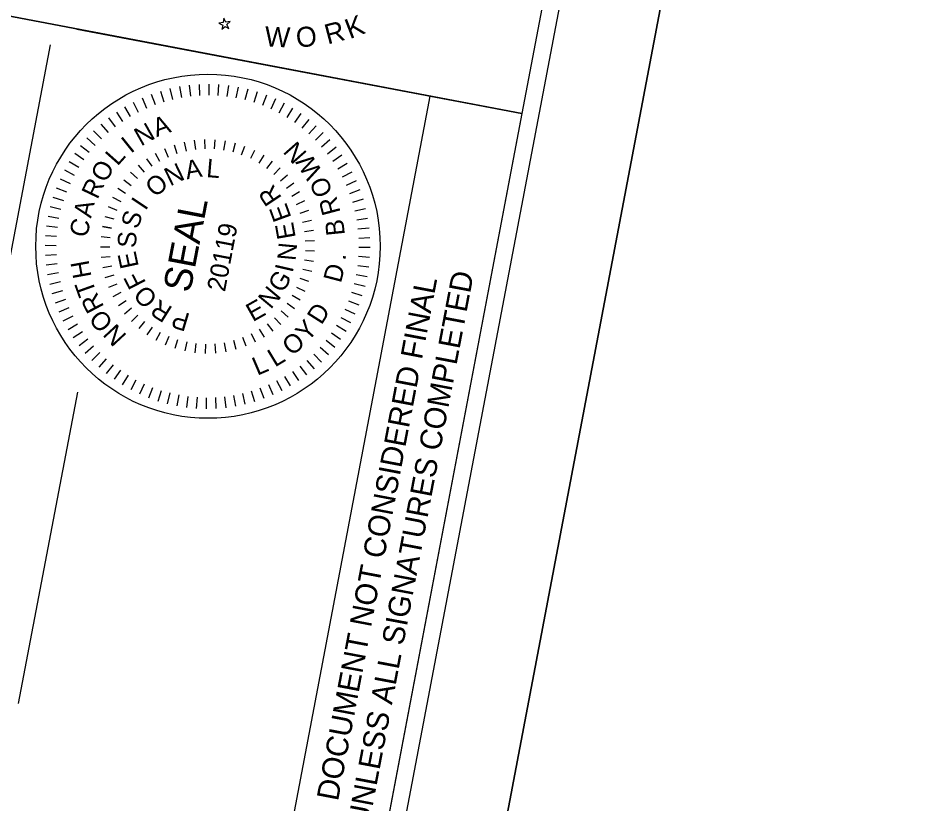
# Model space of a CAD drawing. Extents: x 1615642 to 1617075, y 899305 to 901510.
# Drawn here: x 1616848.8 to 1617075.3, y 900421.5 to 900619.3 of the extents above; entities that cross this region are included whole.
import ezdxf

# ---------------------------------------------------------------- set-up
doc = ezdxf.new("R2010")
doc.units = 0
for name, color, linetype in [('Default', 7, 'Continuous'), ('DEV BORDER CELL', 7, 'Continuous'), ('DEV DOT SWIRL SEAL CELL', 7, 'Continuous'), ('Sheet Plot Border Outside CELL', 7, 'Continuous'), ('Sheet Sticker Exception Certification CELL', 7, 'Continuous'), ('Text', 7, 'Continuous')]:
    doc.layers.add(name, color=color, linetype=linetype)

msp = doc.modelspace()

# ---------------------------------------------------------------- linework, layer by layer
at = {"layer": 'Default'}
for p, q in [((1616887.07, 900601.49), (1616887.72, 900598.78)), ((1616889.49, 900601.99), (1616889.97, 900599.25)), ((1616891.93, 900602.35), (1616892.24, 900599.58)), ((1616894.39, 900602.55), (1616894.54, 900599.77)), ((1616896.86, 900602.61), (1616896.84, 900599.82)), ((1616899.33, 900602.51), (1616899.14, 900599.74)), ((1616901.78, 900602.27), (1616901.43, 900599.51)), ((1616904.22, 900601.88), (1616903.7, 900599.15)), ((1616906.64, 900601.35), (1616905.95, 900598.65)), ((1616880.06, 900599.13), (1616881.18, 900596.58)), ((1616882.35, 900600.06), (1616883.32, 900597.45)), ((1616884.69, 900600.85), (1616885.5, 900598.18)), ((1616909.01, 900600.67), (1616908.16, 900598.01)), ((1616911.34, 900599.85), (1616910.33, 900597.25)), ((1616913.61, 900598.89), (1616912.45, 900596.35)), ((1616875.67, 900596.87), (1616877.1, 900594.47)), ((1616877.83, 900598.07), (1616879.11, 900595.59)), ((1616915.82, 900597.79), (1616914.51, 900595.33)), ((1616873.59, 900595.54), (1616875.15, 900593.24)), ((1616917.96, 900596.56), (1616916.5, 900594.18)), ((1616920.02, 900595.2), (1616918.43, 900592.92)), ((1616869.68, 900592.52), (1616871.51, 900590.43)), ((1616871.59, 900594.09), (1616873.29, 900591.89)), ((1616922.01, 900593.73), (1616920.27, 900591.54)), ((1616923.89, 900592.13), (1616922.03, 900590.06)), ((1616867.87, 900590.85), (1616869.82, 900588.86)), ((1616925.68, 900590.42), (1616923.69, 900588.47)), ((1616866.17, 900589.06), (1616868.24, 900587.2)), ((1616890.62, 900588.01), (1616891.14, 900585.75)), ((1616893.19, 900588.46), (1616893.48, 900586.16)), ((1616895.78, 900588.66), (1616895.85, 900586.34)), ((1616898.39, 900588.61), (1616898.23, 900586.3)), ((1616900.97, 900588.31), (1616900.59, 900586.02)), ((1616903.52, 900587.76), (1616902.92, 900585.52)), ((1616927.35, 900588.62), (1616925.26, 900586.78)), ((1616864.57, 900587.18), (1616866.75, 900585.44)), ((1616885.68, 900586.38), (1616886.63, 900584.26)), ((1616888.11, 900587.31), (1616888.85, 900585.11)), ((1616905.1, 900584.82), (1616905.91, 900587)), ((1616908.39, 900585.94), (1616907.37, 900583.86)), ((1616928.92, 900586.7), (1616926.72, 900585)), ((1616861.73, 900583.14), (1616864.11, 900581.67)), ((1616863.1, 900585.2), (1616865.37, 900583.6)), ((1616881.15, 900583.83), (1616882.48, 900581.92)), ((1616883.36, 900585.21), (1616884.49, 900583.19)), ((1616910.67, 900584.69), (1616909.45, 900582.71)), ((1616912.81, 900583.22), (1616911.41, 900581.37)), ((1616930.37, 900584.71), (1616928.07, 900583.14)), ((1616860.51, 900581), (1616862.97, 900579.68)), ((1616879.09, 900582.24), (1616880.6, 900580.47)), ((1616914.81, 900581.55), (1616913.24, 900579.84)), ((1616931.69, 900582.62), (1616929.3, 900581.2)), ((1616859.41, 900578.78), (1616861.94, 900577.62)), ((1616875.48, 900578.5), (1616877.29, 900577.06)), ((1616877.19, 900580.46), (1616878.87, 900578.85)), ((1616916.64, 900579.69), (1616914.91, 900578.14)), ((1616932.89, 900580.46), (1616930.42, 900579.19)), ((1616858.45, 900576.51), (1616861.05, 900575.5)), ((1616873.96, 900576.39), (1616875.91, 900575.13)), ((1616918.28, 900577.67), (1616916.41, 900576.3)), ((1616933.96, 900578.24), (1616931.41, 900577.11)), ((1616857.63, 900574.18), (1616860.28, 900573.33)), ((1616872.65, 900574.14), (1616874.71, 900573.07)), ((1616919.72, 900575.5), (1616917.72, 900574.31)), ((1616934.89, 900575.95), (1616932.27, 900574.98)), ((1616856.95, 900571.81), (1616859.65, 900571.12)), ((1616871.56, 900571.77), (1616873.72, 900570.91)), ((1616920.94, 900573.2), (1616918.84, 900572.21)), ((1616935.68, 900573.61), (1616933.01, 900572.8)), ((1616921.93, 900570.8), (1616919.74, 900570.01)), ((1616936.32, 900571.22), (1616933.61, 900570.58)), ((1616856.41, 900569.4), (1616859.15, 900568.87)), ((1616870.71, 900569.31), (1616872.94, 900568.66)), ((1616922.69, 900568.3), (1616920.43, 900567.74)), ((1616936.82, 900568.81), (1616934.08, 900568.32)), ((1616856.02, 900566.96), (1616858.78, 900566.6)), ((1616870.1, 900566.78), (1616872.38, 900566.35)), ((1616872.38, 900566.35), (1616870.1, 900566.78)), ((1616923.2, 900565.75), (1616920.9, 900565.4)), ((1616937.18, 900566.37), (1616934.4, 900566.05)), ((1616855.78, 900564.5), (1616858.56, 900564.31)), ((1616869.74, 900564.2), (1616872.05, 900563.99)), ((1616923.46, 900563.16), (1616921.14, 900563.04)), ((1616937.38, 900563.9), (1616934.6, 900563.76)), ((1616855.69, 900562.03), (1616858.47, 900562.01)), ((1616869.62, 900561.61), (1616871.94, 900561.61)), ((1616923.48, 900560.56), (1616921.16, 900560.66)), ((1616937.44, 900561.43), (1616934.65, 900561.46)), ((1616855.74, 900559.57), (1616858.52, 900559.71)), ((1616869.76, 900559.01), (1616872.07, 900559.24)), ((1616923.24, 900557.97), (1616920.94, 900558.29)), ((1616937.34, 900558.97), (1616934.57, 900559.16)), ((1616855.95, 900557.1), (1616858.72, 900557.42)), ((1616870.15, 900556.43), (1616872.43, 900556.89)), ((1616922.75, 900555.41), (1616920.49, 900555.95)), ((1616937.1, 900556.51), (1616934.34, 900556.87)), ((1616856.3, 900554.66), (1616859.05, 900555.14)), ((1616870.78, 900553.91), (1616873, 900554.58)), ((1616922.02, 900552.91), (1616919.82, 900553.67)), ((1616936.71, 900554.07), (1616933.98, 900554.59)), ((1616856.81, 900552.24), (1616859.51, 900552.89)), ((1616871.66, 900551.45), (1616873.81, 900552.34)), ((1616918.93, 900551.45), (1616921.04, 900550.48)), ((1616936.18, 900551.66), (1616933.48, 900552.35)), ((1616857.45, 900549.86), (1616860.12, 900550.67)), ((1616872.77, 900549.1), (1616874.82, 900550.19)), ((1616919.85, 900548.19), (1616917.84, 900549.36)), ((1616935.49, 900549.29), (1616932.84, 900550.13)), ((1616858.24, 900547.52), (1616860.85, 900548.49)), ((1616874.1, 900546.86), (1616876.04, 900548.15)), ((1616918.43, 900546), (1616916.54, 900547.36)), ((1616934.68, 900546.96), (1616932.08, 900547.96)), ((1616859.17, 900545.23), (1616861.71, 900546.36)), ((1616875.64, 900544.76), (1616877.44, 900546.23)), ((1616916.81, 900543.96), (1616915.06, 900545.5)), ((1616933.71, 900544.69), (1616931.18, 900545.84)), ((1616860.23, 900543.01), (1616862.71, 900544.28)), ((1616861.43, 900540.84), (1616863.82, 900542.27)), ((1616877.37, 900542.82), (1616879.03, 900544.45)), ((1616879.29, 900541.06), (1616880.78, 900542.84)), ((1616913.02, 900540.4), (1616911.6, 900542.24)), ((1616915, 900542.09), (1616913.41, 900543.79)), ((1616932.62, 900542.47), (1616930.15, 900543.78)), ((1616862.75, 900538.76), (1616865.06, 900540.33)), ((1616881.36, 900539.49), (1616882.67, 900541.41)), ((1616883.58, 900538.13), (1616884.7, 900540.16)), ((1616910.88, 900538.92), (1616909.65, 900540.88)), ((1616931.39, 900540.33), (1616929.01, 900541.79)), ((1616864.2, 900536.76), (1616866.41, 900538.46)), ((1616885.92, 900536.98), (1616886.84, 900539.12)), ((1616888.36, 900536.07), (1616889.06, 900538.28)), ((1616903.76, 900535.78), (1616903.14, 900538.01)), ((1616906.23, 900536.59), (1616905.4, 900538.76)), ((1616908.62, 900537.64), (1616907.58, 900539.72)), ((1616928.55, 900536.29), (1616926.37, 900538.02)), ((1616930.03, 900538.27), (1616927.75, 900539.87)), ((1616865.77, 900534.85), (1616867.87, 900536.68)), ((1616890.87, 900535.4), (1616891.37, 900537.67)), ((1616893.44, 900534.97), (1616893.71, 900537.28)), ((1616896.04, 900534.8), (1616896.08, 900537.12)), ((1616898.64, 900534.87), (1616898.46, 900537.19)), ((1616901.23, 900535.2), (1616900.82, 900537.49)), ((1616926.96, 900534.4), (1616924.89, 900536.27)), ((1616867.45, 900533.04), (1616869.43, 900535)), ((1616869.23, 900531.34), (1616871.1, 900533.41)), ((1616925.25, 900532.62), (1616923.3, 900534.6)), ((1616871.12, 900529.74), (1616872.85, 900531.92)), ((1616921.53, 900529.37), (1616919.83, 900531.58)), ((1616923.44, 900530.94), (1616921.61, 900533.04)), ((1616873.1, 900528.27), (1616874.69, 900530.55)), ((1616875.16, 900526.91), (1616876.62, 900529.28)), ((1616917.45, 900526.6), (1616916.03, 900528.99)), ((1616919.53, 900527.93), (1616917.97, 900530.23)), ((1616877.3, 900525.68), (1616878.61, 900528.14)), ((1616879.52, 900524.58), (1616880.67, 900527.11)), ((1616913.07, 900524.34), (1616911.94, 900526.88)), ((1616915.29, 900525.4), (1616914.02, 900527.88)), ((1616881.79, 900523.62), (1616882.79, 900526.22)), ((1616884.12, 900522.8), (1616884.96, 900525.45)), ((1616886.49, 900522.12), (1616887.17, 900524.82)), ((1616888.9, 900521.58), (1616889.42, 900524.32)), ((1616903.63, 900521.47), (1616903.15, 900524.22)), ((1616906.05, 900521.98), (1616905.41, 900524.69)), ((1616908.44, 900522.62), (1616907.63, 900525.29)), ((1616910.78, 900523.41), (1616909.81, 900526.02)), ((1616891.34, 900521.19), (1616891.7, 900523.96)), ((1616893.8, 900520.95), (1616893.99, 900523.73)), ((1616896.26, 900520.86), (1616896.28, 900523.64)), ((1616898.73, 900520.91), (1616898.59, 900523.7)), ((1616901.19, 900521.12), (1616900.88, 900523.89))]:
    msp.add_line(p, q, dxfattribs=at)
at = {"layer": 'DEV BORDER CELL'}
for p, q in [((1616863.68, 900616.49), (1616975.68, 900595.23)), ((1616829.71, 900468.75), (1616857, 900612.52)), ((1616849, 900446.64), (1616863.88, 900525.03))]:
    msp.add_line(p, q, dxfattribs=at)
for points in [[(1616014.55, 901139.21), (1615734.74, 899665.53), (1616766.32, 899469.67), (1617046.12, 900943.35)], [(1616840.59, 900620.87), (1616861.86, 900732.87), (1616996.95, 900707.23), (1616975.68, 900595.22)], [(1616803.28, 900424.35), (1616840.59, 900620.87), (1616975.68, 900595.22), (1616938.37, 900398.7)]]:
    msp.add_lwpolyline(points, close=True, dxfattribs=at)
msp.add_circle((1616896.65, 900561.78), 43.34, dxfattribs=at)
at = {"layer": 'DEV DOT SWIRL SEAL CELL'}
for p, q in [((1616900.47, 900618.15), (1616899.42, 900617.98)), ((1616899.42, 900617.98), (1616900.35, 900617.48)), ((1616900.35, 900617.48), (1616900.14, 900616.42)), ((1616900.14, 900616.42), (1616900.94, 900617.16)), ((1616900.67, 900619.21), (1616900.47, 900618.15)), ((1616901.14, 900618.23), (1616900.67, 900619.21)), ((1616901.14, 900618.23), (1616900.68, 900619.22)), ((1616900.94, 900617.16), (1616901.91, 900616.65)), ((1616902.23, 900618.35), (1616901.14, 900618.23)), ((1616902.23, 900618.35), (1616901.14, 900618.23)), ((1616901.43, 900617.6), (1616902.23, 900618.35)), ((1616901.43, 900617.6), (1616902.23, 900618.35)), ((1616901.91, 900616.65), (1616901.43, 900617.6))]:
    msp.add_line(p, q, dxfattribs=at)
at = {"layer": 'Sheet Plot Border Outside CELL'}
for points in [[(1616760.47, 899304.87), (1615679.78, 899510.06), (1615994.65, 901168.43), (1617075.34, 900963.24)], [(1616760.47, 899304.87), (1617075.34, 900963.24), (1615994.65, 901168.43), (1615679.78, 899510.06)]]:
    msp.add_lwpolyline(points, close=True, dxfattribs=at)
at = {"layer": 'Sheet Sticker Exception Certification CELL'}
for p, q in [((1616915.28, 900403.08), (1616952.59, 900599.61)), ((1616952.6, 900599.61), (1616975.69, 900595.22)), ((1616975.68, 900595.22), (1616938.37, 900398.7))]:
    msp.add_line(p, q, dxfattribs=at)

# ---------------------------------------------------------------- texts
at = {"layer": 'Default'}
for s, height, rotation, p in [('A', 4.64, 19.7134, (1616883.74, 900589.24)), ('N', 4.64, 29.481, (1616879.8, 900586.88)), ('I', 4.64, 38.7754, (1616877.22, 900585)), ('N', 4.64, 131.4034, (1616921.77, 900585.19)), ('L', 4.64, 48.3509, (1616873.87, 900581.83)), ('O', 4.64, 61.4872, (1616870.95, 900577.58)), ('A', 4.64, 10.3632, (1616891.32, 900578.61)), ('L', 4.64, 355.067, (1616896.11, 900579.23)), ('W', 4.64, 122.5208, (1616925.62, 900580.49)), ('N', 4.64, 25.6595, (1616887.11, 900576.83)), ('R', 4.64, 64.544, (1616868.8, 900573.42)), ('O', 4.64, 40.9557, (1616883.39, 900573.9)), ('O', 4.64, 113.6381, (1616928.19, 900575.35)), ('R', 4.64, 123.7612, (1616915.36, 900573.97)), ('I', 4.64, 56.252, (1616880.91, 900570.56)), ('R', 4.64, 104.8155, (1616930.05, 900570.31)), ('A', 4.64, 76.5533, (1616867.21, 900568.72)), ('SEAL', 6.965, 79.1963, (1616892.17, 900549.87)), ('E', 4.64, 109.9902, (1616917.71, 900569.02)), ('S', 4.64, 71.5482, (1616879, 900565.9)), ('C', 4.64, 76.5533, (1616866.16, 900563.75)), ('20119', 4.64, 79.1963, (1616900.91, 900550.14)), ('E', 4.64, 100.0043, (1616918.76, 900563.97)), ('B', 4.64, 95.813, (1616931.11, 900564.65)), ('S', 4.64, 86.8445, (1616878.51, 900561.28)), ('E', 4.64, 102.1407, (1616879.26, 900556.7)), ('N', 4.64, 84.6122, (1616918.68, 900558.01)), ('.', 4.64, 83.0287, (1616931.23, 900558.08)), ('H', 4.64, 100.264, (1616867.36, 900554.13)), ('I', 4.64, 76.9825, (1616917.93, 900554.94)), ('D', 4.64, 75.2863, (1616930.09, 900552.34)), ('F', 4.64, 117.437, (1616881.15, 900552.56)), ('G', 4.64, 58.8877, (1616915.44, 900549.79)), ('T', 4.64, 109.6959, (1616868.65, 900550.08)), ('O', 4.64, 132.7332, (1616884.24, 900548.83)), ('N', 4.64, 50.1215, (1616912.45, 900545.74)), ('R', 4.64, 117.8569, (1616870.61, 900546.53)), ('R', 4.64, 148.0295, (1616887.99, 900546.25)), ('E', 4.64, 29.2664, (1616907.92, 900542.64)), ('D', 4.64, 57.491, (1616925.2, 900541.79)), ('O', 4.64, 130.9136, (1616873.05, 900542.64)), ('P', 4.64, 163.3257, (1616892.38, 900544.69)), ('Y', 4.64, 48.5185, (1616921.72, 900537.53)), ('N', 4.64, 132.8731, (1616876.4, 900539.29)), ('O', 4.64, 39.8459, (1616917.75, 900533.99)), ('L', 4.64, 31.2032, (1616913.5, 900531.22)), ('L', 4.64, 23.1314, (1616909.05, 900529.14))]:
    msp.add_text(s, height=height, rotation=rotation, dxfattribs=at).set_placement(p)
at = {"layer": 'Sheet Sticker Exception Certification CELL'}
for s, p in [('UNLESS ALL SIGNATURES COMPLETED', (1616937.07, 900415.23)), ('DOCUMENT NOT CONSIDERED FINAL', (1616929.37, 900421.85))]:
    msp.add_text(s, height=5.5, rotation=79.2494, dxfattribs=at).set_placement(p)
at = {"layer": 'Text'}
for s, rotation, p in [('K', 21.0412, (1616932.34, 900613.91)), ('W', 357.3994, (1616910.86, 900612.13)), ('O', 6.3641, (1616919.07, 900611.76)), ('R', 14.8034, (1616926.77, 900612.58))]:
    msp.add_text(s, height=5.04, rotation=rotation, dxfattribs=at).set_placement(p)

doc.saveas('drawing.dxf')
